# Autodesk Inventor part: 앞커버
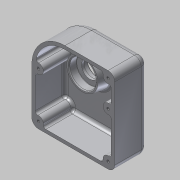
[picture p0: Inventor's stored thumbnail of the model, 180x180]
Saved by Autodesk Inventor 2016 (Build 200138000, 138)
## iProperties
Created: 2015-10
Part Number: 앞커버
Material: 알루미늄 6061
Document SubType Name: Modeling
Designer: mduedu
Density: 2.71 g/cm^3
Mass: 307.08 g
Surface Area: 494.818 cm^2
Volume: 113.314 cm^3
Appearance: Aluminum - Flat
Author: mduedu
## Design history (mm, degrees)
sketch "스케치1"
  geometry: L1 (0, 40)-(60, 40); L2 (60, 40)-(60, -63); L3 (60, -63)-(-40, -63); L4 (-40, -63)-(-40, 0); A1 r 40 centre (0, 0) between (0, 40) and (-40, 0); 1 further point
  constraints: 8 end point, 2 point on circle, 2 tangent, 1 centre point, 1 coincident, 1 horizontal, 1 parallel, 1 perpendicular, 1 vertical
  dimensions: "d0" = 40 radius of A1; "d1" = 103 distance of L1.end L2.end; "d2" = 100 distance of L2.end L3.end
extrude "돌출2" new body sketch "스케치1" distance "d8" = 40; taper "d9" = 0 deg
fillet "모깎기3" dims "d10" = 8
fillet "모깎기4" dims "d11" = 8
feature "쉘2" dims "d12" = 4
sketch "스케치2"
  geometry: C1 r 21.5 at (32, 55); 1 further point
  constraints: 1 centre point, 1 coincident
  dimensions: "d13" = 43 diameter of C1
extrude "돌출3" join sketch "스케치2" distance "d14" = 15; taper "d15" = 0 deg
hole "구멍1" diameter "d18" = 32; stored, may be unused: countersink angle "d22" = 90 deg, drill point angle "d24" = 0 deg; dims "d16" = 10, "d17" = 10, "d19" = 6, "d20" = 4, "d21" = 2, "d23" = 9
hole "구멍2" diameter "d27" = 20; stored, may be unused: countersink angle "d31" = 90 deg, drill point angle "d33" = 0 deg; dims "d25" = 10, "d26" = 10, "d28" = 6, "d29" = 4, "d30" = 2, "d32" = 3
hole "구멍3" diameter "d36" = 25; stored, may be unused: countersink angle "d40" = 90 deg, drill point angle "d42" = 0 deg; dims "d34" = 10, "d35" = 10, "d37" = 6, "d38" = 4, "d39" = 2, "d41" = 3
chamfer "모따기1" distance "d43" = 1; stored, may be unused: second distance "d44" = 2, angle "d45" = 45 deg
feature "면 기울기1" dims angle "d46" = 10 deg
sketch "스케치3"
  geometry: L1 (-40, 0)-(-40, -55) reference; L2 (60, -55)-(60, 32) reference; L3 (-40, 0)-(60, 0); C1 r 6 at (52, 32); C2 r 6 at (52, -55); C3 r 6 at (-32, -55); C4 r 6 at (52, 0); C5 r 6 at (-32, 0); A1 r 8 centre (52, 32) between (60, 32) and (52, 40) reference; A2 r 8 centre (52, -55) between (52, -63) and (60, -55) reference; A3 r 8 centre (-32, -55) between (-40, -55) and (-32, -63) reference; 1 further point
  constraints: 5 centre point, 4 equal radius, 3 coincident, 3 point on line, 2 end point, 2 vertical alignment, 1 perpendicular
  dimensions: "d47" = 6 radius of C1
extrude "돌출4" join sketch "스케치3" stored distance "d49" = 15; taper "d50" = 0 deg
fillet "모깎기5" dims "d51" = 3
fillet "모깎기6" dims "d52" = 3
sketch "스케치4"
  geometry: A1 r 6 centre (-32, 0) between (-32.667, -5.963) and (-31.833, 5.998) reference; A2 r 6 centre (52, 32) between (46.037, 32.667) and (52.667, 26.037) reference; A3 r 6 centre (52, 0) between (52.667, 5.963) and (52.667, -5.963) reference; A4 r 6 centre (52, -55) between (52.667, -49.037) and (46.037, -55.667) reference; A5 r 6 centre (-32, -55) between (-26.037, -55.667) and (-32.667, -49.037) reference; 6 further points
  constraints: 5 coincident
hole "구멍4" sketch "스케치4" at (-32, 0), (52, 32), (52, 0), (52, -55), (-32, -55) diameter "d53" = 3.242; stored, may be unused: countersink angle "d57" = 90 deg, drill point angle "d59" = 118 deg; dims "d54" = 12, "d55" = 4, "d56" = 2, "d58" = 14
sketch "스케치5"
  geometry: L1 (-52, -63)-(32, -63) reference; L2 (-60, 32)-(-60, -55) reference; 2 further points
  constraints: 1 other
  dimensions: "d60" = 20 distance from line of point (-10, -43) L1; "d61" = 50 distance from line of point (-10, -43) L2
feature "엠보싱1" sketch "스케치5" dims "d13" = 43, "d62" = 0.5, "d63" = 0
fillet "모깎기7" dims "d64" = 0.3
node "솔리드2"
